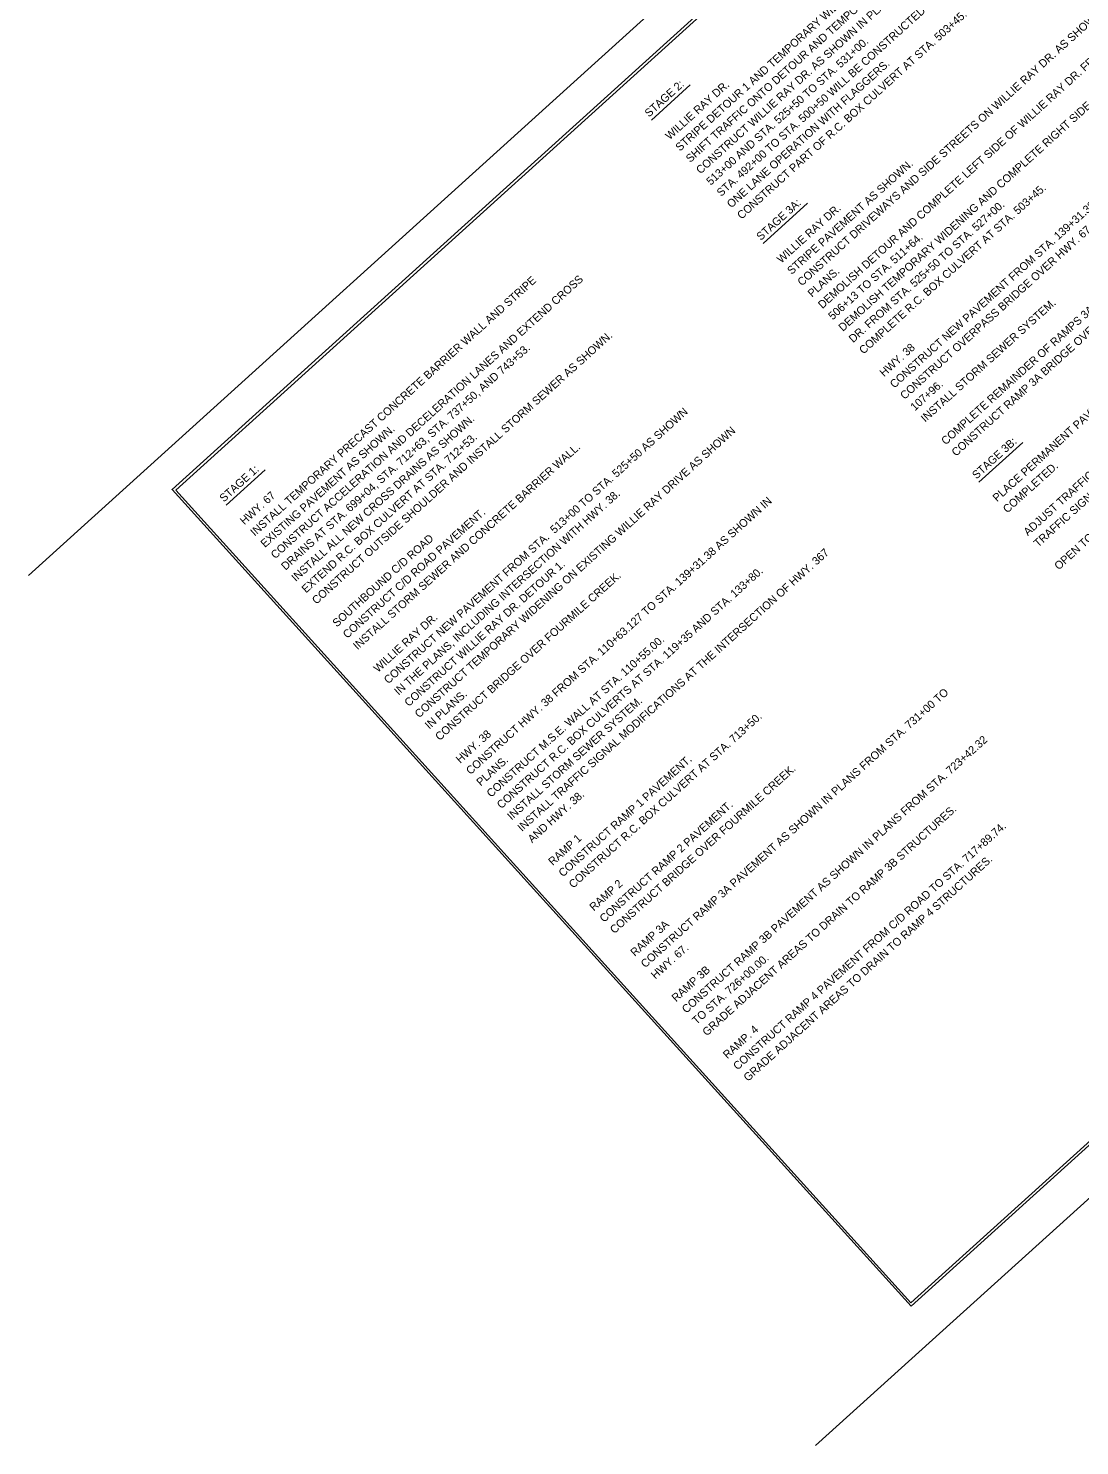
# Model space of a CAD drawing. Extents: x 1307930 to 1312775, y 238372 to 242903.
# Drawn here: x 1307930 to 1308915, y 238372 to 239700 of the extents above; entities that cross this region are included whole.
import ezdxf

# ---------------------------------------------------------------- set-up
doc = ezdxf.new("R2010")
doc.units = 0
for name, color, linetype in [('R_Border', 7, 'Continuous'), ('R_Draft', 7, 'Continuous'), ('R_No Plot', 7, 'Continuous')]:
    doc.layers.add(name, color=color, linetype=linetype)

msp = doc.modelspace()

# ---------------------------------------------------------------- linework, layer by layer
at = {"layer": 'R_Border'}
for p, q in [((1309234.8, 240368.2), (1307929.6, 239187.5)), ((1308067.7, 239267.6), (1309240.2, 240328.1)), ((1309929.3, 239566.2), (1308756.8, 238505.7)), ((1308667.5, 238371.8), (1309972.8, 239552.5)), ((1308756.8, 238505.7), (1308067.7, 239267.6))]:
    msp.add_line(p, q, dxfattribs=at)
at = {"layer": 'R_Draft'}
for p, q in [((1308513.6, 239614.3), (1308550, 239647.3)), ((1308618.2, 239498.6), (1308660, 239536.4)), ((1308820.4, 239275), (1308861.6, 239312.2)), ((1308115, 239253.4), (1308151.5, 239286.4))]:
    msp.add_line(p, q, dxfattribs=at)
at = {"layer": 'R_No Plot'}
msp.add_lwpolyline([(1308757.1, 238502.4), (1309932.5, 239565.7), (1309239.9, 240331.5), (1308064.4, 239268.1)], close=True, dxfattribs=at)

# ---------------------------------------------------------------- texts
at = {"layer": 'R_Draft'}
for s, p in [('CONSTRUCT WILLIE RAY DR. AS SHOWN IN PLANS FROM STA. 492+00 TO STA. ', (1308559.6, 239563.4)), ('STA. 492+00 TO STA. 500+50 WILL BE CONSTRUCTED UNDER TRAFFIC USING ', (1308578.9, 239542.2)), ('STRIPE DETOUR 1 AND TEMPORARY WIDENING AS SHOWN.', (1308540.3, 239584.7)), ('SHIFT TRAFFIC ONTO DETOUR AND TEMPORARY WIDENING.', (1308550, 239574.1)), ('CONSTRUCT DRIVEWAYS AND SIDE STREETS ON WILLIE RAY DR. AS SHOWN ON ', (1308654.6, 239458.4)), ('CONSTRUCT PART OF R.C. BOX CULVERT AT STA. 503+45.', (1308598.1, 239520.9)), ('DEMOLISH DETOUR AND COMPLETE LEFT SIDE OF WILLIE RAY DR. FROM STA. ', (1308673.9, 239437.1)), ('513+00 AND STA. 525+50 TO STA. 531+00.', (1308569.2, 239552.8)), ('DEMOLISH TEMPORARY WIDENING AND COMPLETE RIGHT SIDE OF WILLIE RAY ', (1308693.1, 239415.8)), ('ONE LANE OPERATION WITH FLAGGERS.', (1308588.5, 239531.5)), ('STAGE 2:', (1308511.4, 239616.7)), ('WILLIE RAY DR.', (1308530.7, 239595.4)), ('CONSTRUCT NEW PAVEMENT FROM STA. 139+31.38 TO STA. 101+32.54.', (1308741.3, 239362.6)), ('CONSTRUCT OVERPASS BRIDGE OVER HWY. 67 AND M.S.E. WALL AT STA. ', (1308750.9, 239352)), ('STRIPE PAVEMENT AS SHOWN.', (1308645, 239469.1)), ('COMPLETE R.C. BOX CULVERT AT STA. 503+45.', (1308712.4, 239394.5)), ('STAGE 3A:', (1308616.1, 239501)), ('DR. FROM STA. 525+50 TO STA. 527+00.', (1308702.7, 239405.2)), ('WILLIE RAY DR.', (1308635.3, 239479.7)), ('506+13 TO STA. 511+64.', (1308683.5, 239426.5)), ('PLACE PERMANENT PAVEMENT MARKINGS AFTER ALL WORK HAS BEEN ', (1308837.6, 239256.1)), ('CONSTRUCT RAMP 3A BRIDGE OVER FOURMILE CREEK. ', (1308799.1, 239298.7)), ('PLANS.', (1308664.2, 239447.8)), ('COMPLETE REMAINDER OF RAMPS 3A, 3B, AND 4.', (1308789.4, 239309.4)), ('INSTALL TEMPORARY PRECAST CONCRETE BARRIER WALL AND STRIPE ', (1308141.8, 239223.9)), ('CONSTRUCT ACCELERATION AND DECELERATION LANES AND EXTEND CROSS ', (1308161, 239202.6)), ('ADJUST TRAFFIC SIGNAL EQUIPMENT AS SHOWN IN PLANS AND PLACE ', (1308866.5, 239224.2)), ('INSTALL STORM SEWER SYSTEM.', (1308770.2, 239330.7)), ('CONSTRUCT OUTSIDE SHOULDER AND INSTALL STORM SEWER AS SHOWN.', (1308199.6, 239160)), ('HWY. 38', (1308731.6, 239373.3)), ('DRAINS AT STA. 699+04, STA. 712+63, STA. 737+50, AND 743+53.', (1308170.7, 239191.9)), ('107+96.', (1308760.5, 239341.3)), ('TRAFFIC SIGNAL INTO FINAL OPERATION.', (1308876.1, 239213.5)), ('INSTALL ALL NEW CROSS DRAINS AS SHOWN.', (1308180.3, 239181.3)), ('CONSTRUCT NEW PAVEMENT FROM STA.  513+00 TO STA. 525+50 AS SHOWN ', (1308267, 239085.4)), ('EXISTING PAVEMENT AS SHOWN.', (1308151.4, 239213.2)), ('CONSTRUCT TEMPORARY WIDENING ON EXISTING WILLIE RAY DRIVE AS SHOWN ', (1308295.9, 239053.5)), ('EXTEND R.C. BOX CULVERT AT STA. 712+53.', (1308189.9, 239170.6)), ('STAGE 3B:', (1308818.3, 239277.4)), ('INSTALL STORM SEWER AND CONCRETE BARRIER WALL.', (1308238.1, 239117.4)), ('STAGE 1:', (1308112.9, 239255.8)), ('COMPLETED.', (1308847.2, 239245.5)), ('HWY. 67', (1308132.1, 239234.5)), ('IN THE PLANS, INCLUDING INTERSECTION WITH HWY. 38.', (1308276.6, 239074.8)), ('CONSTRUCT HWY. 38 FROM STA. 110+63.127 TO STA. 139+31.38 AS SHOWN IN ', (1308344, 239000.3)), ('OPEN TO TRAFFIC.', (1308895.4, 239192.2)), ('CONSTRUCT C/D ROAD PAVEMENT.', (1308228.5, 239128)), ('SOUTHBOUND C/D ROAD', (1308218.8, 239138.7)), ('INSTALL TRAFFIC SIGNAL MODIFICATIONS AT THE INTERSECTION OF HWY. 367 ', (1308392.2, 238947)), ('CONSTRUCT WILLIE RAY DR. DETOUR 1.', (1308286.2, 239064.1)), ('CONSTRUCT R.C. BOX CULVERTS AT STA. 119+35 AND STA. 133+80.', (1308372.9, 238968.3)), ('CONSTRUCT BRIDGE OVER FOURMILE CREEK.', (1308315.1, 239032.2)), ('WILLIE RAY DR.', (1308257.3, 239096.1)), ('CONSTRUCT M.S.E. WALL AT STA. 110+55.00.', (1308363.3, 238979)), ('IN PLANS.', (1308305.5, 239042.9)), ('INSTALL STORM SEWER SYSTEM.', (1308382.6, 238957.7)), ('CONSTRUCT RAMP 3A PAVEMENT AS SHOWN IN PLANS FROM STA. 731+00 TO ', (1308507.8, 238819.2)), ('CONSTRUCT R.C. BOX CULVERT AT STA. 713+50.', (1308440.3, 238893.8)), ('HWY. 38', (1308334.4, 239010.9)), ('CONSTRUCT RAMP 3B PAVEMENT AS SHOWN IN PLANS FROM STA. 723+42.32 ', (1308546.3, 238776.6)), ('CONSTRUCT RAMP 1 PAVEMENT.', (1308430.7, 238904.4)), ('PLANS.', (1308353.7, 238989.6)), ('CONSTRUCT BRIDGE OVER FOURMILE CREEK.', (1308478.9, 238851.2)), ('AND HWY. 38.', (1308401.8, 238936.4)), ('CONSTRUCT RAMP 2 PAVEMENT.', (1308469.2, 238861.8)), ('GRADE ADJACENT AREAS TO DRAIN TO RAMP 3B STRUCTURES.', (1308565.5, 238755.3)), ('CONSTRUCT RAMP 4 PAVEMENT FROM C/D ROAD TO STA. 717+89.74.', (1308594.4, 238723.4)), ('RAMP 1', (1308421.1, 238915.1)), ('GRADE ADJACENT AREAS TO DRAIN TO RAMP 4 STRUCTURES.', (1308604.1, 238712.7)), ('RAMP 2', (1308459.6, 238872.5)), ('RAMP 3A', (1308498.1, 238829.9)), ('HWY. 67.', (1308517.4, 238808.6)), ('RAMP 3B', (1308536.7, 238787.3)), ('TO STA. 726+00.00.', (1308555.9, 238766)), ('RAMP. 4', (1308584.8, 238734))]:
    msp.add_text(s, height=7.5, rotation=42.1285, dxfattribs=at).set_placement(p)

doc.saveas('drawing.dxf')
